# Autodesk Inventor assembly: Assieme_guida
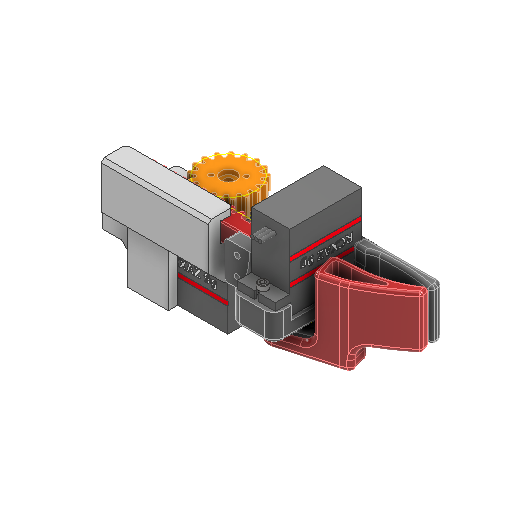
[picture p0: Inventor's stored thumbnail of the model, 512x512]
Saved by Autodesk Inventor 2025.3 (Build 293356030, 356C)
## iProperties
Created: 2026-04
Part Number: Assieme_guida
Document SubType Name: Assembly
Designer: R5800u
Author: R5800u
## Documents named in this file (8)
- C:\Users\R5800u\Desktop\mini_robot_RCXAZ_9g_centrale\Assieme_guida.iam
- C:\Users\R5800u\Desktop\mini_robot_RCXAZ_9g_centrale\RCXAZ_9g.ipt
- C:\Users\R5800u\Desktop\mini_robot_RCXAZ_9g_centrale\RCXAZ_9g doppio.ipt
- C:\Users\R5800u\Desktop\mini_robot_RCXAZ_9g_centrale\pignone_17mm.ipt
- C:\Users\R5800u\Desktop\mini_robot_RCXAZ_9g_centrale\cremagliera.ipt
- C:\Users\R5800u\Desktop\mini_robot_RCXAZ_9g_centrale\Assieme_pinza.iam
- C:\Users\R5800u\Desktop\mini_robot_RCXAZ_9g_centrale\3d print\frame_guida_mg90s.ipt
- C:\Users\R5800u\Desktop\mini_robot_RCXAZ_9g_centrale\3d print\blocco2_guida_mg90s.ipt
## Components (7 placed, 7 different names)
1. RCXAZ_9g:1 — Rotazionale:1, Angolo:2, Angolo:3, Angolo:4, Allineato:2
2. RCXAZ_9g doppio:1 — Rotazionale:1, Rotazionale:2, Angolo:1, Angolo:2
3. pignone_17mm:1 — Rotazionale:2, Angolo:1, Allineato:1, Tangente:1
4. cremagliera:1 — Angolo:3, Angolo:4, Allineato:1, Tangente:1, Allineato:2, Coincidente:1, Allineato:3, Coincidente:2
5. Assieme_pinza:1 [sub-assembly] — Coincidente:1, Allineato:3, Coincidente:2
6. frame_guida_mg90s:1
7. blocco2_guida_mg90s:1
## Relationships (12: Angle 4, Flush 3, RevoluteJoint 2, Mate 2, Tangent 1)
- Rotazionale:1 [RevoluteJoint]: RCXAZ_9g:1 ↔ RCXAZ_9g doppio:1
- Rotazionale:2 [RevoluteJoint]: RCXAZ_9g doppio:1 ↔ pignone_17mm:1
- Angolo:1 [Angle]: RCXAZ_9g doppio:1 ↔ pignone_17mm:1
- Angolo:2 [Angle]: RCXAZ_9g:1 ↔ RCXAZ_9g doppio:1
- Angolo:3 [Angle]: RCXAZ_9g:1 ↔ cremagliera:1
- Angolo:4 [Angle]: RCXAZ_9g:1 ↔ cremagliera:1
- Allineato:1 [Flush]: pignone_17mm:1 ↔ cremagliera:1
- Tangente:1: pignone_17mm:1 ↔ cremagliera:1
- Allineato:2 [Flush]: RCXAZ_9g:1 ↔ cremagliera:1
- Coincidente:1 [Mate]: cremagliera:1 ↔ Assieme_pinza:1
- Allineato:3 [Flush]: cremagliera:1 ↔ Assieme_pinza:1
- Coincidente:2 [Mate]: cremagliera:1 ↔ Assieme_pinza:1
